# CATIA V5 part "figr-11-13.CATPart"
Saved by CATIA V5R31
Part number: Part1
Bounding box of the stored display mesh (mm): x -10 to 5, y -10.258 to 7.91, z -1.915 to 2.054
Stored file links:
  D:\PROJECTS\Project 2021\US EDITION\CATIA V5 6R 2021\Resources\Part Files\c11_catia_v5_6r2021_prt\figr-11-13.CATPart
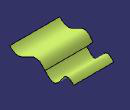
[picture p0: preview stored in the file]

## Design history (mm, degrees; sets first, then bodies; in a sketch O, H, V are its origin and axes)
Set1
  Sketch1 on yz-plane, origin (0, 0, 0), H (0, 1, 0), V (0, 0, 1)
    spline S1 through (-0.358, 0) (-3.1664, 2.0538) (-6.7822, 0.4079) (-10.2576, 1.6423)
    point P1 (-0.358, 0)
    coincidence: P1 H
  Extrude1: Element1 Sketch1, Lim1 5, Lim2 10, Direction yz-plane
  Sketch2 on yz-plane, origin (0, 0, 0), H (0, 1, 0), V (0, 0, 1)
    spline S1 through (0, 0) (3.5471, -1.4404) (5.7957, 1.2855) (7.9098, 0)
    point P1 (0, 0)
    point P2 (7.9098, 0)
    coincidence: P1 O, P2 H
  Extrude2: Element1 Sketch2, Lim1 4, Lim2 8, Direction yz-plane
  Healing1: BodyToHeal (Extrude2; Extrude1), TangencyAngle 0.5, SharpnessAngle 0.5
Body1 (main body)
